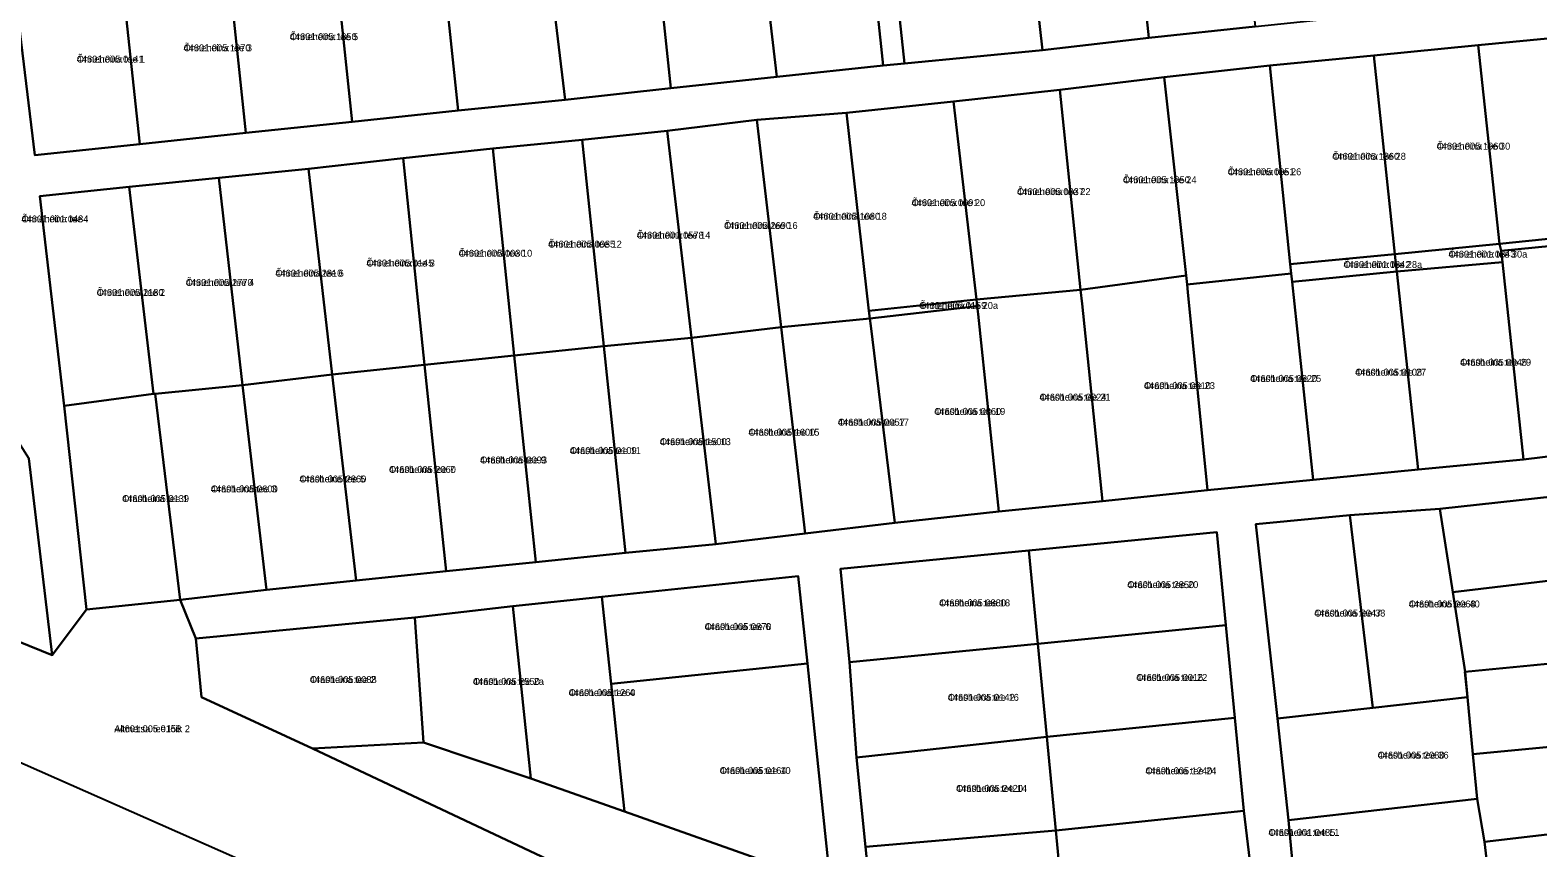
# Model space of a CAD drawing. Extents: x 551843 to 558501, y 6589003 to 6595718.
# Drawn here: x 552683 to 553010, y 6592837.4 to 6593014.7 of the extents above; entities that cross this region are included whole.
import ezdxf

# ---------------------------------------------------------------- set-up
doc = ezdxf.new("R2010")
doc.units = 0
for name, color, linetype in [('L_AADRESS', 7, 'Continuous'), ('PIIR', 7, 'Continuous'), ('TUNNUS', 7, 'Continuous')]:
    doc.layers.add(name, color=color, linetype=linetype)

msp = doc.modelspace()

# ---------------------------------------------------------------- linework, layer by layer
at = {"layer": 'PIIR'}
for points in [[(552868.67, 6593044.62), (552872.65, 6593007.42), (552868.01, 6593006.97), (552864.03, 6593044.71), (552860.28, 6593086.08), (552864.54, 6593086.35)], [(552930.62, 6593051.73), (552944.64, 6593053.21), (552948.63, 6593015.42), (552925.6, 6593012.99), (552921.61, 6593050.78)], [(552898.25, 6593048.26), (552909.97, 6593049.72), (552921.61, 6593050.78), (552925.6, 6593012.99), (552902.53, 6593010.35)], [(552898.25, 6593048.26), (552902.53, 6593010.35), (552872.65, 6593007.42), (552868.67, 6593044.62), (552875.32, 6593045.45), (552889, 6593047.11)], [(552817.95, 6593039.9), (552822.69, 6593040.64), (552840.55, 6593042.43), (552844.97, 6593004.53), (552821.94, 6593002.1)], [(552840.55, 6593042.43), (552842.95, 6593042.82), (552864.03, 6593044.71), (552868.01, 6593006.97), (552844.97, 6593004.53)], [(552801.88, 6593038.42), (552817.95, 6593039.9), (552821.94, 6593002.1), (552799.02, 6592999.56), (552794.49, 6593037.53)], [(552782.75, 6593036.13), (552794.49, 6593037.53), (552799.02, 6592999.56), (552775.88, 6592997.25), (552771.89, 6593035.04)], [(552725.83, 6593030.18), (552740.73, 6593031.75), (552748.86, 6593032.61), (552752.85, 6592994.82), (552729.82, 6592992.39)], [(552748.86, 6593032.61), (552761.27, 6593033.92), (552771.89, 6593035.04), (552775.88, 6592997.25), (552752.85, 6592994.82)], [(552702.8, 6593027.74), (552720.18, 6593029.58), (552725.83, 6593030.18), (552729.82, 6592992.39), (552706.79, 6592989.96)], [(552684.04, 6592987.57), (552679.49, 6593025.29), (552699.64, 6593027.41), (552702.8, 6593027.74), (552706.79, 6592989.96)], [(552996.99, 6593011.42), (553019.58, 6593013.61), (553024.28, 6592970.62), (553001.62, 6592968.34)], [(552974.42, 6593009.18), (552996.99, 6593011.42), (553001.62, 6592968.34), (552978.94, 6592966.1)], [(552928.92, 6593004.46), (552951.84, 6593007), (552956.27, 6592963.95), (552956.49, 6592961.87), (552933.92, 6592959.51), (552933.7, 6592961.44)], [(552974.42, 6593009.18), (552978.94, 6592966.1), (552956.27, 6592963.95), (552951.84, 6593007)], [(552933.7, 6592961.44), (552910.81, 6592958.33), (552906.29, 6593001.75), (552928.92, 6593004.46)], [(552906.29, 6593001.75), (552910.81, 6592958.33), (552888.27, 6592956.29), (552883.25, 6592999.18)], [(552860.06, 6592996.75), (552864.92, 6592953.81), (552865.09, 6592952.14), (552845.85, 6592950.23), (552840.59, 6592995.24)], [(552883.25, 6592999.18), (552888.27, 6592956.29), (552864.92, 6592953.81), (552860.06, 6592996.75)], [(552821.14, 6592992.8), (552840.59, 6592995.24), (552845.85, 6592950.23), (552826.44, 6592947.94)], [(552802.73, 6592990.85), (552807.44, 6592946.14), (552788, 6592944.12), (552783.33, 6592988.99)], [(552807.44, 6592946.14), (552802.73, 6592990.85), (552821.14, 6592992.8), (552826.44, 6592947.94)], [(552763.89, 6592986.94), (552768.56, 6592942.09), (552748.49, 6592940.02), (552743.37, 6592984.62)], [(552783.33, 6592988.99), (552788, 6592944.12), (552768.56, 6592942.09), (552763.89, 6592986.94)], [(552729.08, 6592937.68), (552723.92, 6592982.66), (552743.37, 6592984.62), (552748.49, 6592940.02)], [(552704.47, 6592980.7), (552709.81, 6592935.78), (552690.39, 6592933.18), (552685.12, 6592978.68)], [(552709.81, 6592935.78), (552704.47, 6592980.7), (552723.92, 6592982.66), (552729.08, 6592937.68), (552710.12, 6592935.8)], [(553002.02, 6592966.84), (553001.62, 6592968.34), (553024.28, 6592970.62), (553024.12, 6592969)], [(553001.62, 6592968.34), (553002.02, 6592966.84), (553002.29, 6592964.33), (552979.37, 6592962.35), (552979.17, 6592963.99), (552978.94, 6592966.1)], [(553006.83, 6592921.54), (553002.29, 6592964.33), (553002.02, 6592966.84), (553024.12, 6592969), (553029.73, 6592924.42)], [(552956.49, 6592961.87), (552956.27, 6592963.95), (552978.94, 6592966.1), (552979.17, 6592963.99), (552979.37, 6592962.35), (552956.69, 6592960.1)], [(553002.29, 6592964.33), (553006.83, 6592921.54), (552984.03, 6592919.43), (552979.37, 6592962.35)], [(552934.07, 6592957.84), (552938.3, 6592914.96), (552915.54, 6592912.52), (552911.12, 6592955.35), (552910.81, 6592958.33), (552933.7, 6592961.44), (552933.92, 6592959.51)], [(552956.49, 6592961.87), (552956.69, 6592960.1), (552961.26, 6592917.13), (552938.3, 6592914.96), (552934.07, 6592957.84), (552933.92, 6592959.51)], [(552956.69, 6592960.1), (552979.37, 6592962.35), (552984.03, 6592919.43), (552961.26, 6592917.13)], [(552888.27, 6592956.29), (552910.81, 6592958.33), (552911.12, 6592955.35), (552915.54, 6592912.52), (552893.09, 6592910.27), (552888.61, 6592953.12), (552888.35, 6592954.84)], [(552864.92, 6592953.81), (552888.27, 6592956.29), (552888.35, 6592954.84), (552865.09, 6592952.14)], [(552888.61, 6592953.12), (552893.09, 6592910.27), (552870.53, 6592907.81), (552865.31, 6592950.52), (552865.09, 6592952.14), (552888.35, 6592954.84)], [(552865.09, 6592952.14), (552865.31, 6592950.52), (552870.53, 6592907.81), (552851.12, 6592905.53), (552845.85, 6592950.23)], [(552807.44, 6592946.14), (552826.44, 6592947.94), (552831.71, 6592903.24), (552812.1, 6592901.37)], [(552826.44, 6592947.94), (552845.85, 6592950.23), (552851.12, 6592905.53), (552831.71, 6592903.24)], [(552768.56, 6592942.09), (552788, 6592944.12), (552792.65, 6592899.35), (552773.21, 6592897.33)], [(552792.65, 6592899.35), (552788, 6592944.12), (552807.44, 6592946.14), (552812.1, 6592901.37)], [(552748.49, 6592940.02), (552768.56, 6592942.09), (552773.21, 6592897.33), (552753.76, 6592895.31)], [(552710.12, 6592935.8), (552729.08, 6592937.68), (552734.31, 6592893.29), (552715.58, 6592891.12)], [(552729.08, 6592937.68), (552748.49, 6592940.02), (552753.76, 6592895.31), (552734.31, 6592893.29)], [(552656.68, 6592934.64), (552678.96, 6592927.74), (552682.72, 6592921.77), (552687.84, 6592879.17), (552649.31, 6592894.78)], [(552690.39, 6592933.18), (552709.81, 6592935.78), (552710.12, 6592935.8), (552715.58, 6592891.12), (552695.27, 6592889.04)], [(552988.7, 6592910.87), (553030.42, 6592915.42), (553032.78, 6592897.69), (552991.5, 6592892.8)], [(552969.22, 6592909.5), (552974.16, 6592867.71), (552953.51, 6592865.41), (552948.82, 6592907.53)], [(552991.5, 6592892.8), (552994.18, 6592875.56), (552994.73, 6592870.04), (552974.16, 6592867.71), (552969.22, 6592909.5), (552988.7, 6592910.87)], [(552940.37, 6592905.8), (552942.32, 6592885.67), (552901.51, 6592881.58), (552899.56, 6592901.84)], [(552858.75, 6592897.9), (552899.56, 6592901.84), (552901.51, 6592881.58), (552860.7, 6592877.63)], [(552807.01, 6592891.81), (552849.58, 6592896.26), (552851.56, 6592877.36), (552808.99, 6592872.91)], [(553035.16, 6592879.51), (552994.18, 6592875.56), (552991.5, 6592892.8), (553032.78, 6592897.69)], [(552787.71, 6592889.79), (552807.01, 6592891.81), (552808.99, 6592872.91), (552810.97, 6592854.01), (552811.89, 6592845.23), (552791.63, 6592852.4)], [(552791.63, 6592852.4), (552768.35, 6592860.25), (552766.48, 6592887.32), (552787.71, 6592889.79)], [(552718.97, 6592882.77), (552766.48, 6592887.32), (552768.35, 6592860.25), (552744.28, 6592858.91), (552720.19, 6592870.03)], [(552942.32, 6592885.67), (552944.27, 6592865.55), (552903.47, 6592861.47), (552901.51, 6592881.58)], [(552901.51, 6592881.58), (552903.47, 6592861.47), (552862.25, 6592856.94), (552860.7, 6592877.63)], [(553036.95, 6592861.6), (552995.89, 6592857.68), (552994.73, 6592870.04), (552994.15, 6592875.56), (553035.16, 6592879.51)], [(552808.99, 6592872.91), (552851.56, 6592877.36), (552853.54, 6592858.46), (552856.57, 6592829.41), (552811.89, 6592845.23), (552810.97, 6592854.01)], [(552955.9, 6592843.41), (552953.51, 6592865.41), (552974.16, 6592867.71), (552994.73, 6592870.04), (552995.89, 6592857.68), (552996.82, 6592847.98)], [(552903.47, 6592861.47), (552944.27, 6592865.55), (552946.22, 6592845.42), (552905.44, 6592841.11)], [(552744.28, 6592858.91), (552768.35, 6592860.25), (552791.63, 6592852.4), (552811.89, 6592845.23), (552856.57, 6592829.41), (552866, 6592819.59), (552910.42, 6592798.4), (552952.25, 6592784.31), (552954.4, 6592759.84)], [(552903.47, 6592861.47), (552905.44, 6592841.11), (552864.19, 6592837.58), (552862.25, 6592856.94)], [(552995.89, 6592857.68), (553036.95, 6592861.6), (553039.09, 6592843.47), (552998.37, 6592838.7), (552996.82, 6592847.98)], [(552996.82, 6592847.98), (552998.37, 6592838.7), (552999.69, 6592827.58), (552957.74, 6592823.21), (552955.9, 6592843.41)], [(552905.44, 6592841.11), (552946.22, 6592845.42), (552948.62, 6592825.56), (552907.34, 6592821.34)], [(552998.37, 6592838.7), (553039.09, 6592843.47), (553041.21, 6592825.44), (553000.49, 6592820.67), (552999.69, 6592827.58)], [(552866, 6592819.59), (552864.19, 6592837.58), (552905.44, 6592841.11), (552907.34, 6592821.34), (552910.42, 6592798.4)]]:
    msp.add_lwpolyline(points, close=True, dxfattribs=at)
for points in [[(552679.49, 6593025.29), (552684.04, 6592987.57), (552706.79, 6592989.96), (552729.82, 6592992.39), (552752.85, 6592994.82), (552775.88, 6592997.25), (552799.02, 6592999.56), (552821.94, 6593002.1), (552844.97, 6593004.53), (552868.01, 6593006.97), (552872.65, 6593007.42), (552902.53, 6593010.35), (552925.6, 6593012.99), (552948.63, 6593015.42), (552971.67, 6593017.86), (552994.64, 6593020.4), (553017.86, 6593023.03)], [(553019.58, 6593013.61), (552996.99, 6593011.42), (552974.42, 6593009.18), (552951.84, 6593007), (552928.92, 6593004.46), (552906.29, 6593001.75), (552883.25, 6592999.18), (552860.06, 6592996.75), (552840.59, 6592995.24), (552821.14, 6592992.8), (552802.73, 6592990.85), (552783.33, 6592988.99), (552763.89, 6592986.94), (552743.37, 6592984.62), (552723.92, 6592982.66), (552704.47, 6592980.7), (552685.12, 6592978.68), (552690.39, 6592933.18), (552695.27, 6592889.04), (552687.84, 6592879.17), (552682.72, 6592921.77)], [(552856.57, 6592829.41), (552853.54, 6592858.46), (552851.56, 6592877.36), (552849.58, 6592896.26), (552807.01, 6592891.81), (552787.71, 6592889.79), (552766.48, 6592887.32), (552718.97, 6592882.77), (552715.58, 6592891.12), (552734.31, 6592893.29), (552753.76, 6592895.31), (552773.21, 6592897.33), (552792.65, 6592899.35), (552812.1, 6592901.37), (552831.71, 6592903.24), (552851.12, 6592905.53), (552870.53, 6592907.81), (552893.09, 6592910.27), (552915.54, 6592912.52), (552938.3, 6592914.96), (552961.26, 6592917.13), (552984.03, 6592919.43), (553006.83, 6592921.54), (553029.73, 6592924.42)], [(553030.42, 6592915.42), (552988.7, 6592910.87), (552969.22, 6592909.5), (552948.82, 6592907.53), (552953.51, 6592865.41), (552955.9, 6592843.41), (552957.74, 6592823.21)], [(552649.31, 6592894.78), (552687.84, 6592879.17), (552695.27, 6592889.04), (552715.58, 6592891.12), (552718.97, 6592882.77), (552720.19, 6592870.03), (552744.28, 6592858.91), (552954.4, 6592759.84), (552963.58, 6592755.51), (552951.31, 6592731.46), (552790.35, 6592807.5), (552761.08, 6592820.43), (552747.34, 6592826.5), (552554.8, 6592911.54)], [(552948.62, 6592825.56), (552946.22, 6592845.42), (552944.27, 6592865.55), (552942.32, 6592885.67), (552940.37, 6592905.8), (552899.56, 6592901.84), (552858.75, 6592897.9), (552860.7, 6592877.63), (552862.25, 6592856.94), (552864.19, 6592837.58), (552866, 6592819.59)]]:
    msp.add_lwpolyline(points, dxfattribs=at)

# ---------------------------------------------------------------- texts
at = {"layer": 'L_AADRESS'}
for s, p in [('Õnneheina tee 5', (552739.34, 6593012.5)), ('Õnneheina tee 1', (552693.14, 6593007.63)), ('Õnneheina tee 3', (552716.31, 6593010.07)), ('Õnneheina tee 30', (552988.02, 6592988.76)), ('Õnneheina tee 28', (552965.39, 6592986.56)), ('Õnneheina tee 24', (552920, 6592981.48)), ('Õnneheina tee 26', (552942.71, 6592983.21)), ('Õnneheina tee 22', (552897.03, 6592978.9)), ('Õnneheina tee 20', (552874.17, 6592976.51)), ('Õnneheina tee', (552681.17, 6592972.98)), ('Õnneheina tee 16', (552833.5, 6592971.56)), ('Õnneheina tee 18', (552852.84, 6592973.56)), ('Õnneheina tee 14', (552814.58, 6592969.46)), ('Õnneheina tee 10', (552775.95, 6592965.54)), ('Õnneheina tee 12', (552795.38, 6592967.52)), ('Õnneheina tee 30a', (552990.6, 6592965.35)), ('Õnneheina tee 8', (552755.96, 6592963.42)), ('Õnneheina tee 28a', (552967.82, 6592963.1)), ('Õnneheina tee 4', (552716.77, 6592959.2)), ('Õnneheina tee 6', (552736.21, 6592961.22)), ('Õnneheina tee 2', (552697.46, 6592957.05)), ('Õnneheina tee 20a', (552875.85, 6592954.21)), ('Orasheina tee 27', (552970.36, 6592939.75)), ('Orasheina tee 29', (552993.1, 6592941.9)), ('Orasheina tee 23', (552924.55, 6592936.84)), ('Orasheina tee 25', (552947.59, 6592938.39)), ('Orasheina tee 21', (552901.91, 6592934.34)), ('Orasheina tee 19', (552879.09, 6592931.25)), ('Orasheina tee 15', (552838.78, 6592926.74)), ('Orasheina tee 17', (552858.19, 6592928.91)), ('Orasheina tee 11', (552800.05, 6592922.75)), ('Orasheina tee 13', (552819.57, 6592924.69)), ('Orasheina tee 9', (552780.61, 6592920.72)), ('Orasheina tee 5', (552741.42, 6592916.6)), ('Orasheina tee 7', (552760.85, 6592918.67)), ('Orasheina tee 3', (552722.21, 6592914.44)), ('Orasheina tee 1', (552702.98, 6592912.35)), ('Orasheina tee 20', (552920.94, 6592893.69)), ('Orasheina tee 18', (552880.13, 6592889.74)), ('Orasheina tee 38', (552961.49, 6592887.53)), ('Orasheina tee 40', (552981.97, 6592889.5)), ('Orasheina tee 6', (552829.29, 6592884.59)), ('Orasheina tee 2', (552743.68, 6592873.12)), ('Orasheina tee 2a', (552779.05, 6592872.71)), ('Orasheina tee 22', (552922.89, 6592873.57)), ('Orasheina tee 4', (552799.8, 6592870.28)), ('Orasheina tee 16', (552882.02, 6592869.26)), ('Altmetsa tee lõik 2', (552701.29, 6592862.45)), ('Orasheina tee 36', (552975.22, 6592856.73)), ('Orasheina tee 10', (552832.55, 6592853.38)), ('Orasheina tee 24', (552924.86, 6592853.33)), ('Orasheina tee 14', (552883.81, 6592849.52)), ('Orasheina tee L1', (552951.55, 6592839.97))]:
    msp.add_text(s, height=1.5, dxfattribs=at).set_placement(p)
at = {"layer": 'TUNNUS'}
for s, p in [('44601:005:1350', (552739.34, 6593012.5)), ('44601:005:1970', (552716.31, 6593010.07)), ('44601:005:0141', (552693.14, 6593007.63)), ('44601:005:1960', (552988.02, 6592988.76)), ('44601:005:1360', (552965.39, 6592986.56)), ('44601:005:0051', (552942.71, 6592983.21)), ('44601:005:0037', (552897.03, 6592978.9)), ('44601:005:1950', (552920, 6592981.48)), ('44601:005:0091', (552874.17, 6592976.51)), ('44601:001:0484', (552681.17, 6592972.98)), ('44601:005:1080', (552852.84, 6592973.56)), ('44601:001:0578', (552814.58, 6592969.46)), ('44601:005:2690', (552833.5, 6592971.56)), ('44601:005:0030', (552775.95, 6592965.54)), ('44601:005:0085', (552795.38, 6592967.52)), ('44601:001:0843', (552990.6, 6592965.35)), ('44601:005:0145', (552755.96, 6592963.42)), ('44601:001:0842', (552967.82, 6592963.1)), ('44601:005:2770', (552716.77, 6592959.2)), ('44601:005:2810', (552736.21, 6592961.22)), ('44601:005:2180', (552697.46, 6592957.05)), ('44601:005:0159', (552875.85, 6592954.21)), ('44601:005:0108', (552970.36, 6592939.75)), ('44601:005:0045', (552993.1, 6592941.9)), ('44601:005:0610', (552924.55, 6592936.84)), ('44601:005:0620', (552947.59, 6592938.39)), ('44601:005:0024', (552901.91, 6592934.34)), ('44601:005:0860', (552879.09, 6592931.25)), ('44601:005:1600', (552838.78, 6592926.74)), ('44601:005:0057', (552858.19, 6592928.91)), ('44601:005:0109', (552800.05, 6592922.75)), ('44601:005:1500', (552819.57, 6592924.69)), ('44601:005:0093', (552780.61, 6592920.72)), ('44601:005:2860', (552741.42, 6592916.6)), ('44601:005:2060', (552760.85, 6592918.67)), ('44601:005:0600', (552722.21, 6592914.44)), ('44601:005:0139', (552702.98, 6592912.35)), ('44601:005:2850', (552920.94, 6592893.69)), ('44601:005:0880', (552880.13, 6592889.74)), ('44601:005:0047', (552961.49, 6592887.53)), ('44601:005:0068', (552981.97, 6592889.5)), ('44601:005:0870', (552829.29, 6592884.59)), ('44601:005:0088', (552743.68, 6592873.12)), ('44601:005:2550', (552779.05, 6592872.71)), ('44601:005:0016', (552922.89, 6592873.57)), ('44601:005:1260', (552799.8, 6592870.28)), ('44601:005:0142', (552882.02, 6592869.26)), ('44601:005:0158', (552701.29, 6592862.45)), ('44601:005:2080', (552975.22, 6592856.73)), ('44601:005:0164', (552832.55, 6592853.38)), ('44601:005:1240', (552924.86, 6592853.33)), ('44601:005:2420', (552883.81, 6592849.52)), ('44601:001:0485', (552951.55, 6592839.97))]:
    msp.add_text(s, height=1.5, dxfattribs=at).set_placement(p)

doc.saveas('drawing.dxf')
